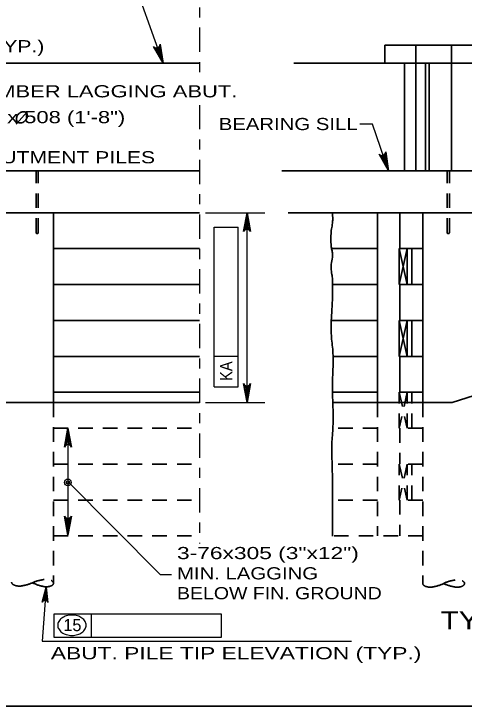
# Model space of a CAD drawing. Extents: x -6.4 to 73.1, y -66 to 0.
# Drawn here: x 12 to 16.45, y -21.25 to -14.42 of the extents above; entities that cross this region are included whole.
import ezdxf
from ezdxf.enums import TextEntityAlignment as Align

# ---------------------------------------------------------------- set-up
doc = ezdxf.new("R2010")
doc.units = 0
doc.header["$LTSCALE"] = 0.048
doc.linetypes.add('DOT_DASHED', pattern=[7.7, 5, -1.2, 0.3, -1.2])
doc.linetypes.add('MEDIUM_DASHED', pattern=[4.5, 3, -1.5])
for name, color, linetype, lineweight in [('1', 7, 'Continuous', 13), ('4', 7, 'Continuous', 25), ('5', 7, 'Continuous', 25)]:
    doc.layers.add(name, color=color, linetype=linetype, lineweight=lineweight)

msp = doc.modelspace()

# ---------------------------------------------------------------- hatches: boundary and pattern name
at = {"layer": '5'}
for points in [[(13.45675, -14.79175), (13.42108, -14.80425), (13.4765, -14.905)], [(15.70225, -15.968), (15.67258, -15.85325), (15.654, -15.85967)], [(14.28483, -16.4995), (14.32425, -16.4995), (14.30458, -16.38133)], [(14.28483, -18.136), (14.32425, -18.136), (14.30458, -18.25408)], [(12.51592, -18.62542), (12.55525, -18.62542), (12.53558, -18.50733)], [(12.51592, -19.44342), (12.55525, -19.44342), (12.53558, -19.5615)]]:
    msp.add_hatch(color=256, dxfattribs=at).paths.add_polyline_path(points)

# ---------------------------------------------------------------- linework, layer by layer
at = {"layer": '1', "lineweight": 35}
msp.add_lwpolyline([(1.75, -21.25), (33.25, -21.25), (33.25, -0.75), (1.75, -0.75)], close=True, dxfattribs=at)
at = {"layer": '4', "lineweight": 35}
for p, q in [((15.66475, -14.72783), (16.60142, -14.72783)), ((15.66475, -14.72783), (15.66475, -14.905)), ((15.96983, -14.72783), (15.96983, -15.968)), ((16.32208, -14.72783), (16.32208, -14.905)), ((8.41083, -14.905), (13.83458, -14.905)), ((14.76558, -14.905), (16.60142, -14.905)), ((15.85975, -14.905), (15.85975, -15.968)), ((16.06808, -14.905), (16.06808, -15.968)), ((16.10192, -14.905), (16.10192, -15.968)), ((16.32208, -14.905), (16.32208, -15.968)), ((7.56575, -15.968), (13.83458, -15.968)), ((14.64683, -15.968), (16.67033, -15.968)), ((7.56575, -16.38133), (13.83458, -16.38133)), ((12.39333, -16.38133), (12.39333, -18.25408)), ((14.70908, -16.38133), (16.69108, -16.38133)), ((15.5935, -16.38133), (15.5935, -18.25408)), ((15.81358, -16.38133), (15.81358, -16.73567)), ((16.13833, -16.38133), (15.99625, -16.38133)), ((16.0395, -16.38133), (16.0395, -18.25408)), ((12.39333, -16.73567), (13.83458, -16.73567)), ((15.5935, -16.73567), (15.13875, -16.73567)), ((15.80675, -17.09), (15.80675, -16.73567)), ((15.80675, -16.73567), (15.887, -17.09)), ((15.887, -16.73567), (15.80675, -17.09)), ((16.0395, -16.73567), (15.80675, -16.73567)), ((15.887, -17.09), (15.887, -16.73567)), ((15.93242, -17.09), (15.93242, -16.73567)), ((16.0395, -16.73567), (15.99625, -16.73567)), ((12.39333, -17.09), (13.83458, -17.09)), ((15.5935, -17.09), (15.14883, -17.09)), ((16.0395, -17.09), (15.80675, -17.09)), ((15.81358, -17.09), (15.81358, -17.44433)), ((19.96233, -17.08525), (16.33033, -18.25408)), ((12.39333, -17.44433), (13.83458, -17.44433)), ((15.5935, -17.44433), (15.13675, -17.44433)), ((15.887, -17.44433), (15.80675, -17.79867)), ((15.80675, -17.79867), (15.80675, -17.44433)), ((16.0395, -17.44433), (15.80675, -17.44433)), ((15.93242, -17.79867), (15.93242, -17.44433)), ((12.39333, -17.79867), (13.83458, -17.79867)), ((15.5935, -17.79867), (15.154, -17.79867)), ((16.0395, -17.79867), (15.80675, -17.79867)), ((15.81358, -17.79867), (15.81358, -18.153)), ((12.39333, -18.153), (13.83458, -18.153)), ((15.5935, -18.153), (15.14833, -18.153)), ((16.0395, -18.153), (15.80675, -18.153)), ((7.8505, -18.25408), (13.83458, -18.25408)), ((15.15108, -18.25408), (16.33033, -18.25408))]:
    msp.add_line(p, q, dxfattribs=at)
at = {"layer": '4', "linetype": 'MEDIUM_DASHED', "lineweight": 35}
for p, q in [((12.22133, -16.5785), (12.22133, -15.968)), ((12.2435, -16.5785), (12.2435, -15.968)), ((16.28075, -16.5785), (16.28075, -15.968)), ((16.30283, -16.5785), (16.30283, -15.968)), ((15.887, -18.153), (15.80675, -18.50733)), ((15.80675, -18.50733), (15.80675, -18.153)), ((15.93242, -18.50733), (15.93242, -18.153)), ((12.39333, -18.25408), (12.39333, -20.03775)), ((15.5935, -18.25408), (15.5935, -19.57033)), ((16.0395, -18.25408), (16.0395, -20.0395)), ((12.39333, -18.50733), (13.83458, -18.50733)), ((15.5935, -18.50733), (15.15183, -18.50733)), ((16.0395, -18.50733), (15.80675, -18.50733)), ((15.81358, -18.50733), (15.81358, -18.86167)), ((12.39333, -18.86167), (13.83458, -18.86167)), ((15.5935, -18.86167), (15.14433, -18.86167)), ((16.0395, -18.86167), (15.80675, -18.86167)), ((15.80675, -19.216), (15.80675, -18.86167)), ((15.80675, -18.86167), (15.887, -19.216)), ((15.887, -18.86167), (15.80675, -19.216)), ((15.887, -19.216), (15.887, -18.86167)), ((15.93242, -19.216), (15.93242, -18.86167)), ((12.39333, -19.216), (13.83458, -19.216)), ((15.5935, -19.216), (15.148, -19.216)), ((16.0395, -19.216), (15.80675, -19.216)), ((15.81358, -19.216), (15.81358, -19.57033)), ((12.39333, -19.57033), (13.83458, -19.57033)), ((16.0395, -19.57033), (15.148, -19.57033))]:
    msp.add_line(p, q, dxfattribs=at)
at = {"layer": '4', "lineweight": 35}
msp.add_lwpolyline([(15.80675, -17.44433), (15.887, -17.79867), (15.887, -17.44433)], dxfattribs=at)
at = {"layer": '4', "linetype": 'MEDIUM_DASHED', "lineweight": 35}
msp.add_lwpolyline([(15.80675, -18.153), (15.887, -18.50733), (15.887, -18.153)], dxfattribs=at)
at = {"layer": '4', "lineweight": 35}
for centre, radius, start, end in [((14.29439, -16.44555), 0.85604, 0, 4.30041), ((14.8467, -16.44555), 0.30373, 352.77729, 0), ((13.83916, -16.31786), 1.31933, 350.22511, 352.77729), ((15.84775, -16.63823), 0.71552, 174.85038, 180), ((15.53535, -16.61008), 0.40185, 170.22511, 174.85038), ((16.01108, -16.63823), 0.87884, 180, 184.64624), ((15.36785, -16.69051), 0.2335, 184.64624, 194.09577), ((14.89674, -16.80881), 0.25224, 5.00495, 14.09577), ((14.94796, -16.80432), 0.20082, 345.34471, 5.00496), ((15.36776, -16.9141), 0.23309, 165.34471, 183.58075), ((15.63195, -16.89757), 0.4978, 183.58075, 190.71943), ((14.84465, -17.04661), 0.30349, 1.57285, 10.71943), ((12.91071, -17.09971), 2.23815, 0, 1.57285), ((8.45851, -17.09971), 6.69035, 359.0903, 0), ((12.15558, -17.15842), 2.99281, 355.92772, 359.0903), ((17.42892, -17.53385), 2.29388, 175.92772, 179.54026), ((16.27863, -17.52462), 1.14355, 179.54026, 187.19626), ((13.83743, -17.83285), 1.31704, 0.06302, 7.19626), ((12.17808, -17.83468), 2.97639, 357.26093, 0.06302), ((17.83322, -18.10523), 2.68522, 177.26093, 180.21106), ((18.86632, -18.10143), 3.71833, 180.21106, 182.50023), ((12.07248, -18.39808), 3.08199, 359.98578, 2.50023), ((12.87931, -18.39828), 2.27516, 355.43722, 359.98579), ((16.95976, -18.72392), 1.81827, 175.43722, 180.5256), ((18.69018, -18.70805), 3.54876, 180.5256, 181.65618), ((-14.04894, -19.65466), 29.20404, 1.26207, 1.65618), ((12.16541, -19.07713), 2.98333, 0, 1.26207), ((-154.10393, -19.07713), 169.25267, 359.83244, 0)]:
    msp.add_arc(centre, radius, start, end, dxfattribs=at)
at = {"layer": '4', "linetype": 'MEDIUM_DASHED', "lineweight": 35}
for centre in [(12.23244, -16.5768), (16.29182, -16.5768)]:
    msp.add_arc(centre, 0.0112, 188.67353, 351.32647, dxfattribs=at)
for centre, major_axis, start_param, end_param in [((12.39064, -20.14106), (0.29221, -0.00772), 1.8903203, 2.3561945), ((12.32017, -20.03582), (0.0732, -0.00193), 4.4555879, 8.1107827), ((16.4527, -20.14279), (0.29215, 0), 1.8903203, 2.3561945), ((16.37952, -20.0395), (0.07318, 0), 4.4555879, 8.1107827), ((12.05331, -20.02877), (-0.0732, 0.00193), 6.2831853, 8.1107827), ((11.98285, -19.92352), (-0.29221, 0.00772), 1.8903203, 2.3561945), ((12.3961, -19.93444), (0.29221, -0.00772), 3.9269908, 4.392865), ((16.11272, -20.0395), (-0.07318, 0), 0, 1.8275974), ((16.03953, -19.93621), (-0.29215, 0), 1.8903203, 2.3561945), ((16.4527, -19.93621), (0.29215, 0), 3.9269908, 4.392865)]:
    msp.add_ellipse(centre, major_axis=major_axis, ratio=0.5, start_param=start_param, end_param=end_param, dxfattribs=at)
at = {"layer": '5', "linetype": 'DOT_DASHED'}
for p, q in [((13.83458, -14.01525), (13.83458, -15.07467)), ((13.83458, -15.31875), (13.83458, -19.64442))]:
    msp.add_line(p, q, dxfattribs=at)
at = {"layer": '5', "lineweight": 35}
msp.add_line((12.02408, -15.50625), (12.13608, -15.38367), dxfattribs=at)
at = {"layer": '5'}
for p, q in [((13.89608, -16.38133), (14.48175, -16.38133)), ((14.30458, -18.25408), (14.30458, -16.38133)), ((13.97967, -18.09908), (13.97967, -16.52433)), ((13.97967, -16.52433), (14.21583, -16.52433)), ((14.21583, -18.09908), (14.21583, -16.52433)), ((13.97967, -17.79667), (14.21583, -17.79667)), ((13.97967, -18.09908), (14.21583, -18.09908)), ((13.89608, -18.25408), (14.48175, -18.25408)), ((12.53558, -18.50733), (12.53558, -19.5615)), ((12.4005, -20.33758), (14.04883, -20.33758)), ((12.4005, -20.57383), (12.4005, -20.33758)), ((12.76733, -20.57383), (12.76733, -20.33758)), ((14.04883, -20.33758), (14.04883, -20.57383)), ((14.04883, -20.57383), (12.4005, -20.57383))]:
    msp.add_line(p, q, dxfattribs=at)
for points in [[(13.47725, -14.905), (13.1435, -13.97367), (13.03008, -13.97367)], [(13.47725, -14.905), (13.3815, -14.74133), (13.39567, -14.7515), (13.40992, -14.75425), (13.42242, -14.752), (13.4335, -14.74575), (13.44275, -14.73458), (13.44725, -14.71775), (13.47725, -14.905), (13.44275, -14.73458), (13.4335, -14.74575), (13.47725, -14.905), (13.42242, -14.752), (13.40992, -14.75425), (13.47725, -14.905), (13.39567, -14.7515)], [(15.70225, -15.968), (15.54292, -15.50675), (15.41783, -15.50675)], [(15.70225, -15.968), (15.60783, -15.8035), (15.622, -15.81383), (15.63617, -15.81667), (15.64875, -15.81458), (15.65983, -15.80842), (15.66917, -15.79733), (15.67383, -15.7805), (15.70225, -15.968), (15.66917, -15.79733), (15.65983, -15.80842), (15.70225, -15.968), (15.64875, -15.81458), (15.63617, -15.81667), (15.70225, -15.968), (15.622, -15.81383)], [(14.30458, -16.38133), (14.3395, -16.56775), (14.32958, -16.55342), (14.31708, -16.546), (14.30458, -16.54383), (14.29208, -16.546), (14.27958, -16.55342), (14.26967, -16.56775), (14.30458, -16.38133), (14.27958, -16.55342), (14.29208, -16.546), (14.30458, -16.38133), (14.30458, -16.54383), (14.31708, -16.546), (14.30458, -16.38133), (14.32958, -16.55342)], [(14.30458, -18.25408), (14.26967, -18.06767), (14.27958, -18.082), (14.29208, -18.08942), (14.30458, -18.09158), (14.31708, -18.08942), (14.32958, -18.082), (14.3395, -18.06767), (14.30458, -18.25408), (14.32958, -18.082), (14.31708, -18.08942), (14.30458, -18.25408), (14.30458, -18.09158), (14.29208, -18.08942), (14.30458, -18.25408), (14.27958, -18.082)], [(12.53558, -18.50733), (12.5705, -18.69375), (12.56058, -18.67942), (12.54808, -18.672), (12.53558, -18.66983), (12.52308, -18.672), (12.51058, -18.67942), (12.50067, -18.69375), (12.53558, -18.50733), (12.51058, -18.67942), (12.52308, -18.672), (12.53558, -18.50733), (12.53558, -18.66983), (12.54808, -18.672), (12.53558, -18.50733), (12.56058, -18.67942)], [(12.53558, -19.03433), (13.44625, -19.95017), (13.55967, -19.95017)], [(12.53558, -19.5615), (12.50067, -19.37508), (12.51058, -19.38942), (12.52308, -19.39683), (12.53558, -19.399), (12.54808, -19.39683), (12.56058, -19.38942), (12.5705, -19.37508), (12.53558, -19.5615), (12.56058, -19.38942), (12.54808, -19.39683), (12.53558, -19.5615), (12.53558, -19.399), (12.52308, -19.39683), (12.53558, -19.5615), (12.51058, -19.38942)], [(12.32, -20.07608), (12.3375, -20.22683), (12.33033, -20.21475), (12.32083, -20.20817), (12.31092, -20.20575), (12.30083, -20.20675), (12.2905, -20.212), (12.28175, -20.22292), (12.32, -20.07608), (12.2905, -20.212), (12.30083, -20.20675), (12.32, -20.07608), (12.31092, -20.20575), (12.32083, -20.20817), (12.32, -20.07608), (12.33033, -20.21475)], [(12.32, -20.07608), (12.28275, -20.60967), (15.33583, -20.60967)]]:
    msp.add_lwpolyline(points, dxfattribs=at)
for points in [[(13.45675, -14.79175), (13.42108, -14.80425), (13.4765, -14.905)], [(15.70225, -15.968), (15.67258, -15.85325), (15.654, -15.85967)], [(14.28483, -16.4995), (14.32425, -16.4995), (14.30458, -16.38133)], [(14.28483, -18.136), (14.32425, -18.136), (14.30458, -18.25408)], [(12.51592, -18.62542), (12.55525, -18.62542), (12.53558, -18.50733)], [(12.51592, -19.44342), (12.55525, -19.44342), (12.53558, -19.5615)]]:
    msp.add_lwpolyline(points, close=True, dxfattribs=at)
for radius in [0.03333, 0.01667]:
    msp.add_circle((12.53562, -19.04242), radius, dxfattribs=at)
for centre, radius, start, end in [((12.57558, -20.54585), 0.19487, 90, 106.53583), ((12.57558, -20.54585), 0.19487, 73.46417, 90), ((12.50852, -20.45144), 0.07309, 149.97668, 180), ((12.54073, -20.47006), 0.1103, 125.63164, 149.97668), ((12.5618, -20.49945), 0.14646, 106.53583, 125.63164), ((12.58935, -20.49945), 0.14646, 54.36836, 73.46417), ((12.61042, -20.47006), 0.1103, 30.02332, 54.36836), ((12.64263, -20.45144), 0.07309, 0, 30.02332), ((12.50852, -20.45144), 0.07309, 180, 210.02332), ((12.54073, -20.43283), 0.1103, 210.02332, 234.36836), ((12.61042, -20.43283), 0.1103, 305.63164, 329.97668), ((12.64263, -20.45144), 0.07309, 329.97668, 0), ((12.5618, -20.40343), 0.14646, 234.36836, 253.46417), ((12.57558, -20.35703), 0.19487, 253.46417, 270), ((12.57558, -20.35703), 0.19487, 270, 286.53583), ((12.58935, -20.40343), 0.14646, 286.53583, 305.63164)]:
    msp.add_arc(centre, radius, start, end, dxfattribs=at)
at = {"layer": '5', "lineweight": 35}
msp.add_spline([(12.12442, -15.39575), (12.11567, -15.38892), (12.10692, -15.3865), (12.09592, -15.3855), (12.08967, -15.3855), (12.07892, -15.388), (12.06908, -15.3925), (12.06217, -15.39642), (12.04892, -15.407), (12.03858, -15.4205), (12.03233, -15.43317), (12.02867, -15.44475), (12.02758, -15.4555), (12.02867, -15.46475), (12.03317, -15.47792), (12.03792, -15.48475), (12.04758, -15.492), (12.06208, -15.4955), (12.07858, -15.495), (12.09942, -15.4855), (12.11467, -15.47242), (12.12617, -15.4565), (12.13367, -15.43992), (12.13617, -15.4215), (12.13292, -15.40967), (12.12492, -15.39575)], degree=3, dxfattribs=at)

# ---------------------------------------------------------------- texts
at = {"layer": '5'}
for s, width, p in [('NAILING BLOCK (TYP.)', 1.3, (10.04267, -14.799)), ('76x305 (3"x12") TIMBER LAGGING ABUT.', 1.35, (10.04658, -15.24325)), ('19.1 (3/4")  x 508 (1\'-8")', 1.35, (10.81167, -15.49833)), ('BEARING SILL', 1.25, (14.02508, -15.5665)), ('TYP. IN ABUTMENT PILES', 1.3, (10.81167, -15.89417)), ('3-76x305 (3"x12")', 1.4, (13.61308, -19.79942)), ('MIN. LAGGING', 1.25, (13.61308, -19.99942)), ('BELOW FIN. GROUND', 1.2, (13.61308, -20.19525)), ('ABUT. PILE TIP ELEVATION (TYP.)', 1.4, (12.36775, -20.78717))]:
    msp.add_text(s, height=0.12, dxfattribs=dict(at, width=width)).set_placement(p)
at = {"layer": '5', "width": 0.9}
msp.add_text('KA', height=0.12, rotation=90, dxfattribs=at).set_placement((14.15792, -17.94458), align=Align.CENTER)
at = {"layer": '5', "width": 1.25}
msp.add_text('TYPICAL WING ELEVATION', height=0.1772, dxfattribs=at).set_placement((18.14875, -20.49292), align=Align.CENTER)
at = {"layer": '5'}
msp.add_text('15', height=0.12, dxfattribs=at).set_placement((12.58012, -20.50992), align=Align.CENTER)

doc.saveas('drawing.dxf')
